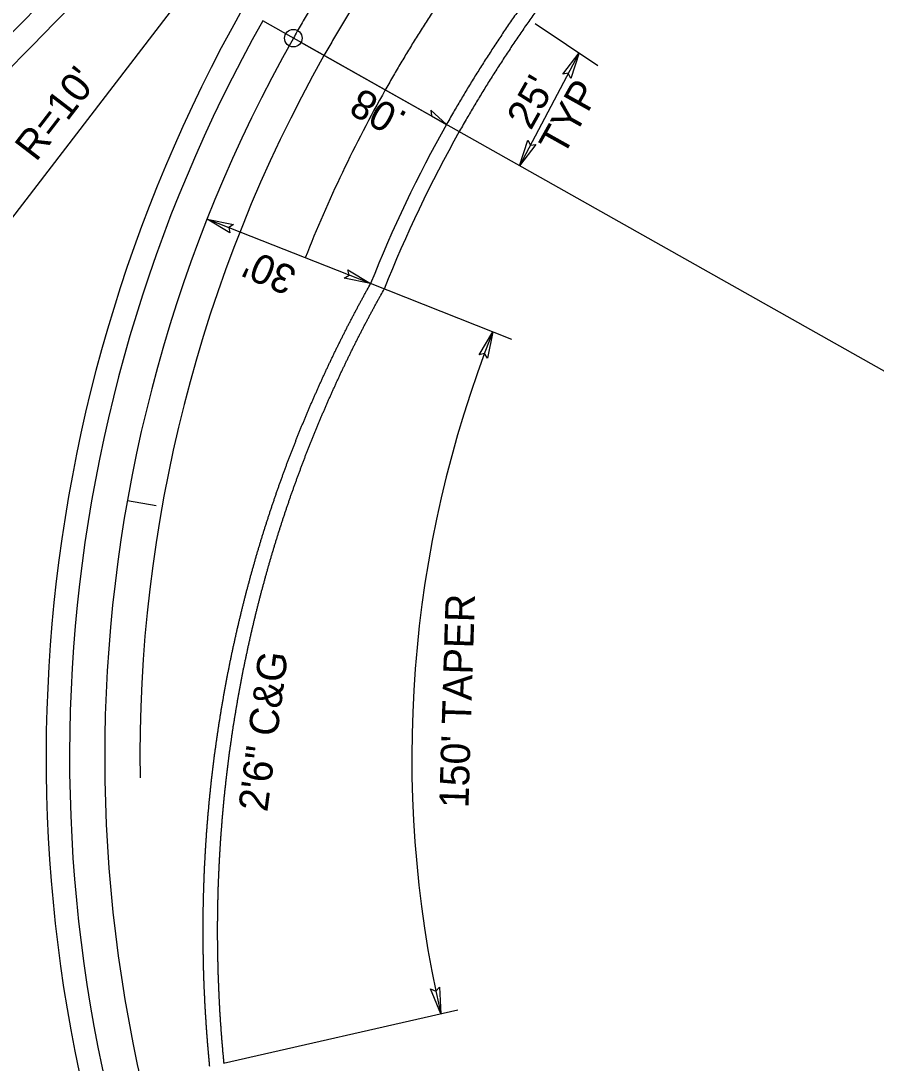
# Model space of a CAD drawing. Extents: x 2389694 to 2405615, y 547005 to 573532.
# Drawn here: x 2401841 to 2401987, y 571095.6 to 571273.5 of the extents above; entities that cross this region are included whole.
import ezdxf

# ---------------------------------------------------------------- set-up
doc = ezdxf.new("R2010")
doc.units = 0
for name, color, linetype in [('Old_Level_11', 7, 'Continuous'), ('Prop Conc 2ft 6in Curb and Gutter', 7, 'Continuous'), ('Prop Dimension', 7, 'Continuous'), ('Prop Dimension Text', 7, 'Continuous'), ('Prop DSN Text', 7, 'Continuous'), ('Prop EOT', 7, 'Continuous'), ('Prop Horizontal Alignment', 7, 'Continuous'), ('Prop Horizontal Alignment Curve and Spiral Data', 7, 'Continuous'), ('Prop Horizontal Alignment Tick Small', 7, 'Continuous'), ('Prop Lane Lines', 7, 'Continuous'), ('Prop Super Arrow 1 Lane CELL', 7, 'Continuous'), ('Prop Superelevation Label', 7, 'Continuous')]:
    doc.layers.add(name, color=color, linetype=linetype)

msp = doc.modelspace()

# ---------------------------------------------------------------- linework, layer by layer
at = {"layer": 'Prop Conc 2ft 6in Curb and Gutter'}
msp.add_arc((2402105.34, 571147.85), 217.5, 150.5977, 158.4443, dxfattribs=at)
for points in [[(2402047.07, 571386.04), (2402044.93, 571384.39), (2402042.8, 571382.74), (2402040.67, 571381.09), (2402038.54, 571379.45), (2402036.42, 571377.81), (2402034.31, 571376.17), (2402032.2, 571374.53), (2402030.1, 571372.89), (2402028, 571371.25), (2402025.9, 571369.61), (2402023.82, 571367.97), (2402021.74, 571366.33), (2402019.66, 571364.69), (2402017.6, 571363.05), (2402015.54, 571361.41), (2402013.49, 571359.77), (2402011.44, 571358.12), (2402009.41, 571356.48), (2402007.38, 571354.83), (2402005.35, 571353.18), (2402003.34, 571351.52), (2402001.34, 571349.86), (2401999.34, 571348.2), (2401997.36, 571346.54), (2401995.38, 571344.87), (2401993.42, 571343.19), (2401991.46, 571341.52), (2401989.52, 571339.83), (2401987.58, 571338.15), (2401985.66, 571336.45), (2401983.74, 571334.76), (2401981.84, 571333.06), (2401979.95, 571331.35), (2401978.07, 571329.63), (2401976.2, 571327.91), (2401974.35, 571326.18), (2401972.51, 571324.45), (2401970.68, 571322.71), (2401968.86, 571320.96), (2401967.06, 571319.21), (2401965.27, 571317.45), (2401963.49, 571315.68), (2401961.73, 571313.91), (2401959.99, 571312.12), (2401958.25, 571310.33), (2401956.54, 571308.53), (2401954.84, 571306.72), (2401953.15, 571304.91), (2401951.48, 571303.09), (2401949.83, 571301.25), (2401948.19, 571299.41), (2401946.57, 571297.56), (2401944.97, 571295.71), (2401943.38, 571293.84), (2401941.82, 571291.97), (2401940.27, 571290.08), (2401938.74, 571288.19), (2401937.22, 571286.29), (2401935.73, 571284.37), (2401934.26, 571282.45), (2401932.81, 571280.53), (2401931.37, 571278.59), (2401929.96, 571276.64), (2401928.57, 571274.68), (2401927.19, 571272.72), (2401925.84, 571270.74), (2401924.52, 571268.76), (2401923.21, 571266.77), (2401921.93, 571264.77), (2401920.66, 571262.76), (2401919.43, 571260.74), (2401918.21, 571258.71), (2401917.02, 571256.68), (2401915.77, 571254.48)], [(2401885.3, 571187.03), (2401885.49, 571187.62), (2401885.67, 571188.19), (2401885.87, 571188.78), (2401886.06, 571189.35), (2401886.25, 571189.93), (2401886.44, 571190.5), (2401886.64, 571191.08), (2401886.84, 571191.66), (2401887.03, 571192.23), (2401887.23, 571192.81), (2401887.44, 571193.37), (2401887.64, 571193.95), (2401887.84, 571194.52), (2401888.05, 571195.09), (2401888.26, 571195.66), (2401888.47, 571196.23), (2401888.68, 571196.8), (2401888.89, 571197.36), (2401889.1, 571197.93), (2401889.32, 571198.49), (2401889.53, 571199.06), (2401889.75, 571199.62), (2401889.97, 571200.19), (2401890.19, 571200.75), (2401890.41, 571201.31), (2401890.64, 571201.87), (2401890.86, 571202.43), (2401891.09, 571202.99), (2401891.32, 571203.55), (2401891.55, 571204.11), (2401891.78, 571204.67), (2401892.01, 571205.22), (2401892.25, 571205.78), (2401892.48, 571206.33), (2401892.72, 571206.88), (2401892.96, 571207.43), (2401893.2, 571207.99), (2401893.44, 571208.54), (2401893.68, 571209.09), (2401893.93, 571209.64), (2401894.17, 571210.18), (2401894.42, 571210.73), (2401894.67, 571211.28), (2401894.92, 571211.83), (2401895.17, 571212.37), (2401895.42, 571212.91), (2401895.67, 571213.46), (2401895.93, 571214), (2401896.19, 571214.54), (2401896.44, 571215.08), (2401896.7, 571215.62), (2401896.97, 571216.16), (2401897.23, 571216.69), (2401897.49, 571217.23), (2401897.76, 571217.77), (2401898.02, 571218.3), (2401898.29, 571218.83), (2401898.56, 571219.37), (2401898.83, 571219.9), (2401899.1, 571220.43), (2401899.38, 571220.96), (2401899.65, 571221.49), (2401899.93, 571222.02), (2401900.2, 571222.54), (2401900.48, 571223.07), (2401900.76, 571223.59), (2401901.04, 571224.12), (2401901.33, 571224.65), (2401901.61, 571225.17), (2401901.9, 571225.69), (2401902.18, 571226.21), (2401902.47, 571226.73), (2401903.05, 571227.76)], [(2401875.9, 571142.4), (2401875.97, 571143.02), (2401876.04, 571143.64), (2401876.11, 571144.26), (2401876.18, 571144.88), (2401876.26, 571145.5), (2401876.33, 571146.12), (2401876.41, 571146.74), (2401876.49, 571147.36), (2401876.57, 571147.98), (2401876.65, 571148.6), (2401876.73, 571149.21), (2401876.82, 571149.83), (2401876.91, 571150.44), (2401877, 571151.06), (2401877.09, 571151.68), (2401877.18, 571152.29), (2401877.27, 571152.91), (2401877.37, 571153.52), (2401877.47, 571154.14), (2401877.56, 571154.75), (2401877.67, 571155.36), (2401877.77, 571155.97), (2401877.87, 571156.59), (2401877.98, 571157.2), (2401878.08, 571157.81), (2401878.19, 571158.42), (2401878.3, 571159.03), (2401878.42, 571159.64), (2401878.53, 571160.24), (2401878.64, 571160.86), (2401878.76, 571161.47), (2401878.88, 571162.07), (2401879, 571162.68), (2401879.12, 571163.28), (2401879.25, 571163.89), (2401879.37, 571164.49), (2401879.5, 571165.1), (2401879.63, 571165.71), (2401879.75, 571166.31), (2401879.89, 571166.91), (2401880.02, 571167.51), (2401880.15, 571168.11), (2401880.29, 571168.71), (2401880.43, 571169.32), (2401880.57, 571169.92), (2401880.71, 571170.51), (2401880.85, 571171.12), (2401881, 571171.71), (2401881.14, 571172.31), (2401881.29, 571172.9), (2401881.44, 571173.5), (2401881.59, 571174.1), (2401881.74, 571174.69), (2401881.9, 571175.29), (2401882.05, 571175.88), (2401882.21, 571176.48), (2401882.37, 571177.06), (2401882.53, 571177.66), (2401882.69, 571178.24), (2401882.85, 571178.84), (2401883.02, 571179.43), (2401883.18, 571180.02), (2401883.35, 571180.61), (2401883.52, 571181.19), (2401883.69, 571181.78), (2401883.86, 571182.36), (2401884.04, 571182.95), (2401884.21, 571183.54), (2401884.39, 571184.12), (2401884.57, 571184.71), (2401884.75, 571185.29), (2401884.93, 571185.87), (2401885.11, 571186.45), (2401885.3, 571187.03)], [(2401875.71, 571095.59), (2401875.65, 571096.23), (2401875.59, 571096.87), (2401875.53, 571097.51), (2401875.48, 571098.14), (2401875.42, 571098.79), (2401875.37, 571099.42), (2401875.32, 571100.06), (2401875.27, 571100.7), (2401875.22, 571101.34), (2401875.18, 571101.98), (2401875.13, 571102.61), (2401875.09, 571103.25), (2401875.05, 571103.88), (2401875.01, 571104.53), (2401874.98, 571105.17), (2401874.94, 571105.8), (2401874.91, 571106.44), (2401874.88, 571107.07), (2401874.85, 571107.71), (2401874.82, 571108.34), (2401874.8, 571108.98), (2401874.77, 571109.62), (2401874.75, 571110.26), (2401874.73, 571110.9), (2401874.71, 571111.53), (2401874.69, 571112.17), (2401874.68, 571112.8), (2401874.66, 571113.44), (2401874.65, 571114.07), (2401874.64, 571114.71), (2401874.63, 571115.35), (2401874.63, 571115.97), (2401874.62, 571116.61), (2401874.62, 571117.24), (2401874.62, 571117.88), (2401874.62, 571118.51), (2401874.62, 571119.15), (2401874.62, 571119.78), (2401874.63, 571120.41), (2401874.63, 571121.05), (2401874.64, 571121.68), (2401874.65, 571122.31), (2401874.67, 571122.94), (2401874.68, 571123.58), (2401874.7, 571124.21), (2401874.71, 571124.84), (2401874.73, 571125.47), (2401874.75, 571126.1), (2401874.78, 571126.73), (2401874.8, 571127.36), (2401874.83, 571127.99), (2401874.86, 571128.63), (2401874.89, 571129.25), (2401874.92, 571129.88), (2401874.95, 571130.51), (2401874.98, 571131.14), (2401875.02, 571131.76), (2401875.06, 571132.4), (2401875.1, 571133.02), (2401875.14, 571133.65), (2401875.19, 571134.28), (2401875.23, 571134.9), (2401875.28, 571135.53), (2401875.33, 571136.15), (2401875.38, 571136.78), (2401875.43, 571137.4), (2401875.48, 571138.03), (2401875.54, 571138.66), (2401875.59, 571139.28), (2401875.65, 571139.91), (2401875.71, 571140.53), (2401875.77, 571141.15), (2401875.84, 571141.77), (2401875.9, 571142.4)]]:
    msp.add_spline(points, degree=3, dxfattribs=at)
at = {"layer": 'Prop Dimension'}
for p, q in [((2401814.5, 571207.32), (2401887.61, 571302.5)), ((2401928.81, 571273.09), (2401939.52, 571265.94)), ((2401936.3, 571268.09), (2401926.16, 571248.82)), ((2401900.73, 571228.68), (2401872.82, 571239.7)), ((2401924.84, 571219.16), (2401900.73, 571228.68)), ((2401875.62, 571095.57), (2401915.62, 571104.67))]:
    msp.add_line(p, q, dxfattribs=at)
for points in [[(2401933.52, 571264.47), (2401936.3, 571268.09), (2401934.9, 571263.71), (2401934.46, 571264.6)], [(2401928.94, 571252.44), (2401926.16, 571248.82), (2401927.56, 571253.2), (2401928, 571252.32)], [(2401876.72, 571237.33), (2401872.82, 571239.7), (2401877.33, 571238.78), (2401876.5, 571238.25)], [(2401896.82, 571231.04), (2401900.73, 571228.68), (2401896.22, 571229.59), (2401897.05, 571230.12)], [(2401919.23, 571216.53), (2401921.58, 571220.44), (2401920.69, 571215.94), (2401920.15, 571216.76)], [(2401912.5, 571108.57), (2401912.69, 571104.01), (2401910.95, 571108.26), (2401911.86, 571107.87)]]:
    msp.add_lwpolyline(points, close=True, dxfattribs=at)
msp.add_arc((2402105.34, 571147.85), 197.58, 158.4442, 192.8217, dxfattribs=at)
at = {"layer": 'Prop EOT'}
for centre, radius, start, end in [((2402411.24, 570717.66), 796, 134.84133, 147.77804), ((2402411.24, 570717.66), 792, 134.84133, 147.77804), ((2402105.34, 571147.85), 260, 150.5977, 254.5865), ((2402105.34, 571147.85), 256, 150.5977, 254.6324), ((2402105.34, 571147.85), 220, 150.5977, 158.4443)]:
    msp.add_arc(centre, radius, start, end, dxfattribs=at)
for points in [[(2402045.54, 571388.02), (2402043.4, 571386.37), (2402041.27, 571384.72), (2402039.14, 571383.07), (2402037.01, 571381.43), (2402034.89, 571379.78), (2402032.78, 571378.14), (2402030.66, 571376.5), (2402028.56, 571374.86), (2402026.46, 571373.22), (2402024.36, 571371.58), (2402022.27, 571369.94), (2402020.19, 571368.3), (2402018.11, 571366.65), (2402016.04, 571365.01), (2402013.98, 571363.37), (2402011.92, 571361.72), (2402009.87, 571360.07), (2402007.83, 571358.42), (2402005.8, 571356.77), (2402003.77, 571355.11), (2402001.75, 571353.45), (2401999.74, 571351.79), (2401997.74, 571350.12), (2401995.75, 571348.45), (2401993.77, 571346.77), (2401991.79, 571345.09), (2401989.83, 571343.41), (2401987.88, 571341.72), (2401985.93, 571340.03), (2401984, 571338.33), (2401982.08, 571336.62), (2401980.17, 571334.91), (2401978.27, 571333.2), (2401976.38, 571331.47), (2401974.5, 571329.74), (2401972.64, 571328.01), (2401970.79, 571326.27), (2401968.95, 571324.52), (2401967.12, 571322.76), (2401965.31, 571321), (2401963.51, 571319.23), (2401961.72, 571317.45), (2401959.95, 571315.66), (2401958.19, 571313.86), (2401956.45, 571312.06), (2401954.72, 571310.25), (2401953.01, 571308.43), (2401951.31, 571306.6), (2401949.63, 571304.77), (2401947.97, 571302.92), (2401946.32, 571301.07), (2401944.68, 571299.2), (2401943.07, 571297.33), (2401941.47, 571295.45), (2401939.89, 571293.56), (2401938.33, 571291.66), (2401936.79, 571289.75), (2401935.26, 571287.83), (2401933.75, 571285.91), (2401932.27, 571283.97), (2401930.8, 571282.02), (2401929.35, 571280.07), (2401927.93, 571278.1), (2401926.52, 571276.12), (2401925.14, 571274.14), (2401923.77, 571272.15), (2401922.43, 571270.14), (2401921.11, 571268.13), (2401919.81, 571266.11), (2401918.54, 571264.08), (2401917.29, 571262.04), (2401916.06, 571259.99), (2401914.86, 571257.93), (2401913.6, 571255.72)], [(2401882.84, 571187.47), (2401883.03, 571188.06), (2401883.22, 571188.64), (2401883.41, 571189.23), (2401883.6, 571189.81), (2401883.79, 571190.4), (2401883.99, 571190.98), (2401884.19, 571191.56), (2401884.38, 571192.15), (2401884.58, 571192.73), (2401884.79, 571193.31), (2401884.99, 571193.88), (2401885.19, 571194.47), (2401885.4, 571195.04), (2401885.61, 571195.62), (2401885.82, 571196.2), (2401886.03, 571196.77), (2401886.24, 571197.35), (2401886.45, 571197.92), (2401886.67, 571198.5), (2401886.88, 571199.06), (2401887.1, 571199.64), (2401887.32, 571200.2), (2401887.54, 571200.78), (2401887.77, 571201.35), (2401887.99, 571201.91), (2401888.21, 571202.48), (2401888.44, 571203.05), (2401888.67, 571203.62), (2401888.9, 571204.18), (2401889.13, 571204.74), (2401889.37, 571205.31), (2401889.6, 571205.87), (2401889.84, 571206.43), (2401890.07, 571206.99), (2401890.31, 571207.55), (2401890.55, 571208.11), (2401890.79, 571208.67), (2401891.04, 571209.23), (2401891.28, 571209.78), (2401891.53, 571210.34), (2401891.77, 571210.89), (2401892.02, 571211.45), (2401892.27, 571212), (2401892.52, 571212.55), (2401892.78, 571213.11), (2401893.03, 571213.65), (2401893.29, 571214.21), (2401893.54, 571214.75), (2401893.8, 571215.3), (2401894.06, 571215.84), (2401894.33, 571216.39), (2401894.59, 571216.94), (2401894.85, 571217.48), (2401895.12, 571218.03), (2401895.39, 571218.56), (2401895.66, 571219.11), (2401895.92, 571219.64), (2401896.2, 571220.19), (2401896.47, 571220.72), (2401896.74, 571221.26), (2401897.02, 571221.8), (2401897.3, 571222.33), (2401897.58, 571222.87), (2401897.85, 571223.4), (2401898.14, 571223.93), (2401898.42, 571224.46), (2401898.7, 571225), (2401898.99, 571225.53), (2401899.27, 571226.05), (2401899.56, 571226.58), (2401899.85, 571227.11), (2401900.14, 571227.64), (2401900.73, 571228.68)], [(2401873.41, 571142.34), (2401873.47, 571142.97), (2401873.54, 571143.59), (2401873.61, 571144.22), (2401873.68, 571144.85), (2401873.76, 571145.48), (2401873.83, 571146.1), (2401873.91, 571146.73), (2401873.99, 571147.36), (2401874.07, 571147.98), (2401874.15, 571148.61), (2401874.24, 571149.23), (2401874.32, 571149.85), (2401874.41, 571150.47), (2401874.5, 571151.1), (2401874.59, 571151.72), (2401874.68, 571152.34), (2401874.77, 571152.97), (2401874.87, 571153.58), (2401874.97, 571154.21), (2401875.07, 571154.82), (2401875.17, 571155.45), (2401875.27, 571156.06), (2401875.37, 571156.68), (2401875.48, 571157.31), (2401875.59, 571157.92), (2401875.7, 571158.54), (2401875.81, 571159.15), (2401875.92, 571159.77), (2401876.03, 571160.38), (2401876.15, 571161), (2401876.27, 571161.62), (2401876.38, 571162.23), (2401876.51, 571162.84), (2401876.63, 571163.45), (2401876.75, 571164.07), (2401876.88, 571164.68), (2401877, 571165.29), (2401877.13, 571165.9), (2401877.26, 571166.51), (2401877.4, 571167.12), (2401877.53, 571167.73), (2401877.66, 571168.34), (2401877.8, 571168.94), (2401877.94, 571169.55), (2401878.08, 571170.16), (2401878.22, 571170.76), (2401878.37, 571171.37), (2401878.51, 571171.97), (2401878.66, 571172.58), (2401878.8, 571173.18), (2401878.96, 571173.79), (2401879.11, 571174.39), (2401879.26, 571174.99), (2401879.41, 571175.59), (2401879.57, 571176.19), (2401879.73, 571176.79), (2401879.89, 571177.39), (2401880.05, 571177.99), (2401880.21, 571178.58), (2401880.38, 571179.18), (2401880.54, 571179.78), (2401880.71, 571180.37), (2401880.88, 571180.97), (2401881.05, 571181.56), (2401881.22, 571182.16), (2401881.39, 571182.75), (2401881.57, 571183.34), (2401881.75, 571183.94), (2401881.92, 571184.53), (2401882.1, 571185.12), (2401882.29, 571185.71), (2401882.47, 571186.3), (2401882.65, 571186.88), (2401882.84, 571187.47)], [(2401873.27, 571095.04), (2401873.21, 571095.69), (2401873.15, 571096.33), (2401873.09, 571096.97), (2401873.03, 571097.61), (2401872.98, 571098.26), (2401872.92, 571098.9), (2401872.87, 571099.55), (2401872.82, 571100.2), (2401872.77, 571100.84), (2401872.73, 571101.49), (2401872.68, 571102.13), (2401872.64, 571102.78), (2401872.6, 571103.42), (2401872.56, 571104.06), (2401872.52, 571104.71), (2401872.48, 571105.35), (2401872.45, 571106), (2401872.42, 571106.64), (2401872.39, 571107.28), (2401872.36, 571107.92), (2401872.33, 571108.57), (2401872.31, 571109.21), (2401872.28, 571109.85), (2401872.26, 571110.5), (2401872.24, 571111.14), (2401872.22, 571111.79), (2401872.21, 571112.42), (2401872.19, 571113.07), (2401872.18, 571113.71), (2401872.17, 571114.35), (2401872.16, 571115), (2401872.15, 571115.63), (2401872.14, 571116.28), (2401872.14, 571116.91), (2401872.14, 571117.56), (2401872.14, 571118.19), (2401872.14, 571118.84), (2401872.14, 571119.48), (2401872.15, 571120.12), (2401872.15, 571120.76), (2401872.16, 571121.4), (2401872.17, 571122.04), (2401872.18, 571122.67), (2401872.19, 571123.32), (2401872.21, 571123.96), (2401872.23, 571124.59), (2401872.25, 571125.23), (2401872.27, 571125.86), (2401872.29, 571126.51), (2401872.31, 571127.14), (2401872.34, 571127.78), (2401872.36, 571128.42), (2401872.39, 571129.05), (2401872.42, 571129.69), (2401872.46, 571130.32), (2401872.49, 571130.96), (2401872.53, 571131.59), (2401872.57, 571132.23), (2401872.61, 571132.86), (2401872.65, 571133.5), (2401872.69, 571134.13), (2401872.73, 571134.76), (2401872.78, 571135.4), (2401872.83, 571136.03), (2401872.88, 571136.66), (2401872.93, 571137.29), (2401872.98, 571137.93), (2401873.04, 571138.56), (2401873.1, 571139.19), (2401873.15, 571139.82), (2401873.21, 571140.45), (2401873.28, 571141.08), (2401873.34, 571141.7), (2401873.41, 571142.34)]]:
    msp.add_spline(points, degree=3, dxfattribs=at)
at = {"layer": 'Prop Horizontal Alignment'}
for centre, radius, start, end in [((2402411.24, 570717.66), 800, 134.84133, 147.77804), ((2402105.34, 571147.85), 250, 150.5977, 261.5766)]:
    msp.add_arc(centre, radius, start, end, dxfattribs=at)
msp.add_spline([(2402027.2, 571411.76), (2402025.06, 571410.11), (2402022.92, 571408.46), (2402020.79, 571406.8), (2402018.65, 571405.15), (2402016.51, 571403.49), (2402014.38, 571401.84), (2402012.24, 571400.18), (2402010.11, 571398.52), (2402007.98, 571396.85), (2402005.85, 571395.19), (2402003.73, 571393.52), (2402001.6, 571391.85), (2401999.48, 571390.17), (2401997.37, 571388.49), (2401995.25, 571386.8), (2401993.14, 571385.12), (2401991.04, 571383.42), (2401988.94, 571381.72), (2401986.84, 571380.02), (2401984.75, 571378.31), (2401982.66, 571376.59), (2401980.58, 571374.87), (2401978.5, 571373.14), (2401976.43, 571371.4), (2401974.36, 571369.65), (2401972.31, 571367.9), (2401970.25, 571366.14), (2401968.21, 571364.38), (2401966.17, 571362.6), (2401964.14, 571360.82), (2401962.12, 571359.02), (2401960.11, 571357.22), (2401958.1, 571355.41), (2401956.11, 571353.59), (2401954.12, 571351.75), (2401952.14, 571349.91), (2401950.17, 571348.06), (2401948.21, 571346.2), (2401946.27, 571344.32), (2401944.33, 571342.44), (2401942.4, 571340.54), (2401940.49, 571338.64), (2401938.58, 571336.72), (2401936.69, 571334.79), (2401934.81, 571332.84), (2401932.95, 571330.89), (2401931.1, 571328.92), (2401929.26, 571326.94), (2401927.43, 571324.95), (2401925.62, 571322.94), (2401923.83, 571320.92), (2401922.04, 571318.89), (2401920.28, 571316.84), (2401918.53, 571314.78), (2401916.8, 571312.71), (2401915.08, 571310.62), (2401913.38, 571308.52), (2401911.7, 571306.4), (2401910.03, 571304.27), (2401908.39, 571302.13), (2401906.76, 571299.97), (2401905.16, 571297.8), (2401903.57, 571295.61), (2401902, 571293.41), (2401900.45, 571291.19), (2401898.93, 571288.96), (2401897.42, 571286.71), (2401895.94, 571284.45), (2401894.48, 571282.18), (2401893.05, 571279.89), (2401891.63, 571277.59), (2401890.24, 571275.27), (2401888.88, 571272.94), (2401887.54, 571270.59)], degree=3, dxfattribs=at)
at = {"layer": 'Prop Horizontal Alignment Curve and Spiral Data'}
msp.add_line((2401888.85, 571269.85), (2402016.23, 571198.07), dxfattribs=at)
msp.add_circle((2401887.54, 571270.59), 1.5, dxfattribs=at)
at = {"layer": 'Prop Horizontal Alignment Tick Small'}
msp.add_line((2401859.21, 571191.68), (2401864.13, 571190.8), dxfattribs=at)
at = {"layer": 'Prop Lane Lines'}
for radius, end in [(244, 180.8318), (232, 158.4442)]:
    msp.add_arc((2402105.34, 571147.85), radius, 150.5977, end, dxfattribs=at)
for points in [[(2402030.87, 571407.01), (2402028.73, 571405.36), (2402026.59, 571403.71), (2402024.46, 571402.06), (2402022.32, 571400.4), (2402020.19, 571398.75), (2402018.06, 571397.1), (2402015.93, 571395.44), (2402013.8, 571393.79), (2402011.67, 571392.13), (2402009.55, 571390.47), (2402007.43, 571388.8), (2402005.32, 571387.14), (2402003.21, 571385.47), (2402001.1, 571383.79), (2401999, 571382.12), (2401996.9, 571380.44), (2401994.8, 571378.75), (2401992.71, 571377.06), (2401990.63, 571375.37), (2401988.55, 571373.67), (2401986.48, 571371.96), (2401984.41, 571370.25), (2401982.35, 571368.53), (2401980.29, 571366.81), (2401978.25, 571365.08), (2401976.2, 571363.34), (2401974.17, 571361.6), (2401972.14, 571359.84), (2401970.13, 571358.09), (2401968.12, 571356.32), (2401966.11, 571354.54), (2401964.12, 571352.76), (2401962.14, 571350.96), (2401960.16, 571349.16), (2401958.2, 571347.35), (2401956.24, 571345.53), (2401954.3, 571343.7), (2401952.36, 571341.86), (2401950.44, 571340.01), (2401948.52, 571338.15), (2401946.62, 571336.28), (2401944.73, 571334.4), (2401942.86, 571332.51), (2401940.99, 571330.6), (2401939.14, 571328.69), (2401937.3, 571326.76), (2401935.48, 571324.82), (2401933.67, 571322.87), (2401931.87, 571320.91), (2401930.09, 571318.94), (2401928.32, 571316.95), (2401926.57, 571314.95), (2401924.84, 571312.94), (2401923.12, 571310.91), (2401921.42, 571308.88), (2401919.73, 571306.83), (2401918.06, 571304.76), (2401916.41, 571302.69), (2401914.78, 571300.6), (2401913.17, 571298.5), (2401911.57, 571296.38), (2401910, 571294.25), (2401908.44, 571292.11), (2401906.9, 571289.95), (2401905.39, 571287.78), (2401903.9, 571285.6), (2401902.43, 571283.4), (2401900.98, 571281.19), (2401899.55, 571278.97), (2401898.15, 571276.73), (2401896.77, 571274.48), (2401895.41, 571272.21), (2401894.08, 571269.93), (2401892.75, 571267.61)], [(2402038.2, 571397.51), (2402036.07, 571395.86), (2402033.93, 571394.21), (2402031.8, 571392.56), (2402029.67, 571390.92), (2402027.54, 571389.27), (2402025.42, 571387.62), (2402023.3, 571385.97), (2402021.18, 571384.32), (2402019.07, 571382.67), (2402016.96, 571381.02), (2402014.85, 571379.37), (2402012.75, 571377.72), (2402010.66, 571376.06), (2402008.57, 571374.4), (2402006.49, 571372.74), (2402004.41, 571371.08), (2402002.34, 571369.41), (2402000.27, 571367.74), (2401998.21, 571366.07), (2401996.16, 571364.39), (2401994.11, 571362.7), (2401992.08, 571361.02), (2401990.04, 571359.33), (2401988.02, 571357.63), (2401986.01, 571355.93), (2401984, 571354.22), (2401982, 571352.5), (2401980.01, 571350.78), (2401978.03, 571349.06), (2401976.06, 571347.32), (2401974.1, 571345.58), (2401972.14, 571343.84), (2401970.2, 571342.08), (2401968.27, 571340.32), (2401966.35, 571338.55), (2401964.44, 571336.77), (2401962.54, 571334.98), (2401960.65, 571333.19), (2401958.78, 571331.39), (2401956.92, 571329.57), (2401955.07, 571327.75), (2401953.23, 571325.92), (2401951.4, 571324.08), (2401949.59, 571322.23), (2401947.8, 571320.37), (2401946.01, 571318.51), (2401944.24, 571316.63), (2401942.49, 571314.74), (2401940.75, 571312.84), (2401939.03, 571310.93), (2401937.32, 571309.01), (2401935.63, 571307.08), (2401933.95, 571305.14), (2401932.29, 571303.18), (2401930.65, 571301.22), (2401929.03, 571299.24), (2401927.42, 571297.26), (2401925.84, 571295.26), (2401924.27, 571293.25), (2401922.72, 571291.23), (2401921.19, 571289.2), (2401919.68, 571287.16), (2401918.18, 571285.1), (2401916.71, 571283.04), (2401915.26, 571280.96), (2401913.84, 571278.87), (2401912.43, 571276.77), (2401911.04, 571274.66), (2401909.68, 571272.54), (2401908.34, 571270.4), (2401907.03, 571268.26), (2401905.73, 571266.1), (2401904.47, 571263.93), (2401903.17, 571261.67)]]:
    msp.add_spline(points, degree=3, dxfattribs=at)
at = {"layer": 'Prop Super Arrow 1 Lane CELL'}
msp.add_line((2401913.68, 571255.86), (2401882.31, 571273.53), dxfattribs=at)
msp.add_lwpolyline([(2401913.68, 571255.86), (2401911.02, 571258.27), (2401911.11, 571257.31)], close=True, dxfattribs=at)

# ---------------------------------------------------------------- texts
at = {"layer": 'Old_Level_11'}
for s, p in [("25'", (2401928.07, 571254.71)), ('TYP', (2401933.6, 571250.26))]:
    msp.add_text(s, height=5, rotation=60.749, dxfattribs=at).set_placement(p)
at = {"layer": 'Prop Dimension Text'}
for s, rotation, p in [("150' TAPER", 88.2448, (2401917.42, 571139.08)), ('2\'6" C&G', 82.5787, (2401883.09, 571138.37))]:
    msp.add_text(s, height=5, rotation=rotation, dxfattribs=at).set_placement(p)
at = {"layer": 'Prop DSN Text'}
msp.add_text("R=10'", height=5, rotation=52.4717, dxfattribs=at).set_placement((2401843.62, 571249.34))
at = {"layer": 'Prop Superelevation Label'}
for s, rotation, p in [('.08', 150.597, (2401907.25, 571257.68)), ("30'", 156.2328, (2401888.45, 571231.13))]:
    msp.add_text(s, height=5, rotation=rotation, dxfattribs=at).set_placement(p)

doc.saveas('drawing.dxf')
